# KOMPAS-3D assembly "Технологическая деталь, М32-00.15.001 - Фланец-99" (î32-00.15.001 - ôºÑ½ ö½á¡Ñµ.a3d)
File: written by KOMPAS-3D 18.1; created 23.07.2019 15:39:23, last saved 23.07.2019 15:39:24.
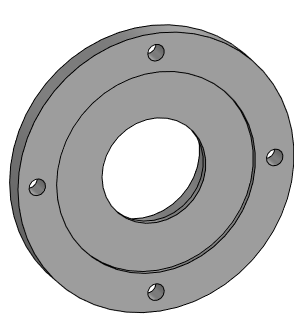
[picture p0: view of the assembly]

Document properties: Автор: Пользователь Windows; Полное имя файла: D:\Magna\Магна Ins\Магна ins 32\М32-00.15.001 - Фланец-99.a3d

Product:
- Part/product: Технологическая деталь  | designation М32-00.15.001 - Фланец-99
    Масса: 7.12591

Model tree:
1. Деталь-заготовка:1

Referenced files in D:\Magna\Магна Ins\Магна ins 32\: М32-00.15.001 - Фланец.m3d
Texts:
  М32-00.15.001 - Фланец-99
